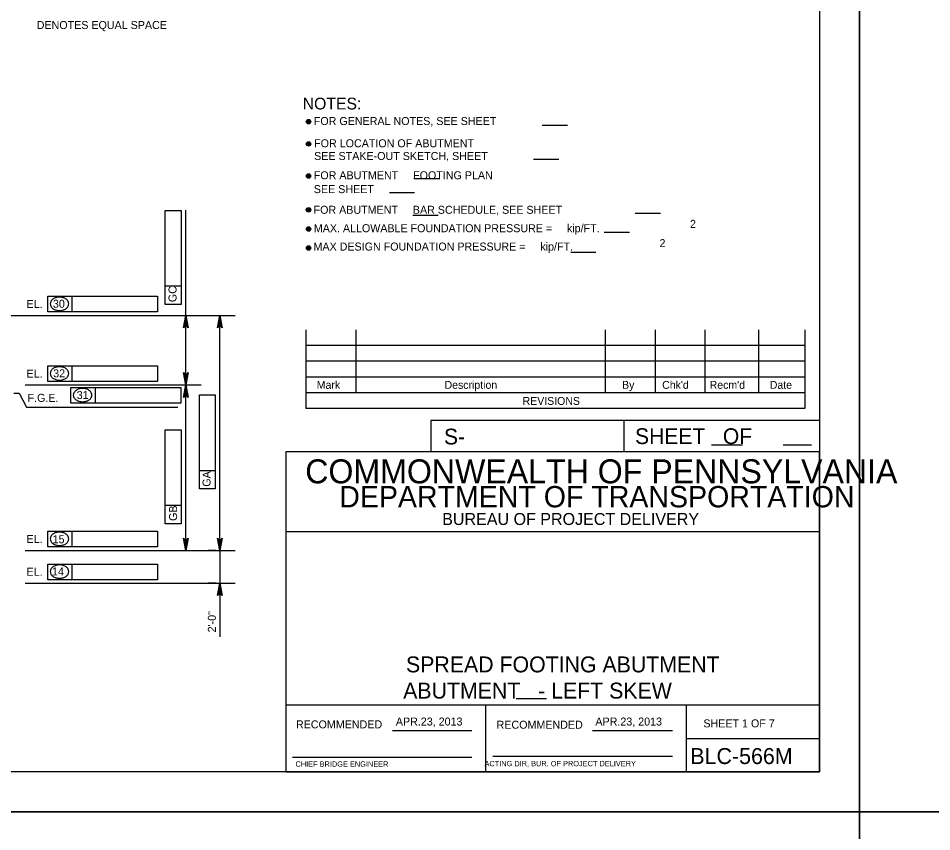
# Model space of a CAD drawing. Extents: x 638255 to 640306, y 296059 to 298435.
# Drawn here: x 638961.1 to 639303.6, y 297834 to 298139 of the extents above; entities that cross this region are included whole.
import ezdxf

# ---------------------------------------------------------------- set-up
doc = ezdxf.new("R2010")
doc.units = 0
for name, color, linetype in [('1', 7, 'Continuous'), ('2', 7, 'Continuous'), ('4', 7, 'Continuous'), ('Level 3', 7, 'Continuous'), ('Level 4', 7, 'Continuous'), ('PLT-BNDY', 7, 'Continuous')]:
    doc.layers.add(name, color=color, linetype=linetype)

# ---------------------------------------------------------------- blocks, each defined once
blk = doc.blocks.new('V')
at = {"layer": '1'}
blk.add_line((0, 0), (0, 0), dxfattribs=at)

msp = doc.modelspace()

# ---------------------------------------------------------------- linework, layer by layer
at = {"layer": '2'}
for p, q in [((639261.46, 298420.46), (639261.46, 297856.46)), ((639068.92, 298022.15), (639068.92, 297992.62)), ((639087.62, 298022.15), (639087.62, 297998.53)), ((639181.13, 298022.15), (639181.13, 297998.53)), ((639199.83, 298022.15), (639199.83, 297998.53)), ((639218.53, 298022.15), (639218.53, 297998.53)), ((639238.59, 298022.15), (639238.59, 297998.53)), ((639255.94, 298022.15), (639255.94, 297992.62)), ((639255.94, 298016.24), (639068.92, 298016.24)), ((639255.94, 298010.34), (639068.92, 298010.34)), ((639255.94, 298004.43), (639068.92, 298004.43)), ((639255.94, 297998.53), (639068.92, 297998.53)), ((639255.94, 297992.62), (639068.92, 297992.62)), ((639261.46, 297988.11), (639115.78, 297988.11)), ((639115.78, 297988.11), (639115.78, 297976.46)), ((639188.09, 297988.11), (639188.09, 297976.46)), ((639220.95, 297979), (639232.6, 297979)), ((639247.83, 297979), (639258.56, 297979)), ((639261.46, 297976.46), (639061.46, 297976.46)), ((639061.46, 297976.46), (639061.46, 297856.46)), ((639261.46, 297856.46), (639261.46, 297976.46)), ((639261.46, 297946.46), (639061.46, 297946.46)), ((639261.46, 297881.46), (639061.46, 297881.46)), ((639136.46, 297856.46), (639136.46, 297881.46)), ((639211.46, 297881.46), (639211.46, 297856.46)), ((639101.42, 297871.96), (639131.19, 297871.96)), ((639176.42, 297871.96), (639206.33, 297871.96)), ((639211.46, 297868.96), (639261.46, 297868.96)), ((639063.96, 297861.96), (639131.19, 297861.96)), ((639139.08, 297862.33), (639206.33, 297862.33)), ((639261.46, 297856.46), (638475.46, 297856.46)), ((639061.46, 297856.46), (639261.46, 297856.46))]:
    msp.add_line(p, q, dxfattribs=at)
at = {"layer": '4'}
msp.add_line((639147.83, 297883.91), (639159.19, 297883.91), dxfattribs=at)
at = {"layer": 'Level 3'}
for p, q in [((639157.57, 298098.88), (639167.02, 298098.88)), ((639154.31, 298086.18), (639163.76, 298086.18)), ((639109.4, 298078.89), (639118.85, 298078.89)), ((639100.26, 298073.62), (639109.71, 298073.62)), ((639016.25, 298066.94), (639022.14, 298066.94)), ((639016.25, 298038.53), (639016.25, 298066.94)), ((639022.14, 298066.94), (639022.14, 298031.7)), ((639023.96, 298001.46), (639023.96, 298066.96)), ((639192.42, 298065.88), (639201.86, 298065.88)), ((639109.04, 298065.1), (639118.49, 298065.1)), ((639180.8, 298058.75), (639190.25, 298058.75)), ((639168.25, 298051.31), (639177.7, 298051.31)), ((639016.25, 298031.7), (639016.25, 298038.53)), ((639022.14, 298038.53), (639016.25, 298038.53)), ((638972.21, 298034.72), (638981.36, 298034.72)), ((638972.21, 298028.83), (638972.21, 298034.72)), ((638981.36, 298028.83), (638981.36, 298034.72)), ((638981.36, 298034.72), (639013.34, 298034.72)), ((639013.34, 298034.72), (639013.34, 298028.83)), ((639022.14, 298031.7), (639016.25, 298031.7)), ((639013.34, 298028.83), (638972.21, 298028.83)), ((638910.57, 298027.55), (639042.49, 298027.55)), ((639021.51, 298027.55), (639028.38, 298027.55)), ((639030.41, 298027.55), (639041.15, 298027.55)), ((639035.64, 298027.55), (639041.15, 298027.55)), ((639036.72, 297939.44), (639036.72, 298027.55)), ((638972.21, 298008.63), (638981.36, 298008.63)), ((638972.21, 298002.73), (638972.21, 298008.63)), ((638981.36, 298002.73), (638981.36, 298008.63)), ((638981.36, 298008.63), (639013.34, 298008.63)), ((639013.34, 298008.63), (639013.34, 298002.73)), ((638963.72, 298001.46), (639029.73, 298001.46)), ((639013.34, 298002.73), (638972.21, 298002.73)), ((639018.63, 298001.46), (639028.38, 298001.46)), ((639023.96, 297939.44), (639023.96, 298001.46)), ((638961.5, 297998.38), (638964.26, 297993.2)), ((638980.88, 298000.5), (638990.04, 298000.5)), ((638980.88, 297994.61), (638980.88, 298000.5)), ((638990.04, 297994.61), (638990.04, 298000.5)), ((638990.04, 298000.5), (639022.01, 298000.5)), ((639022.01, 298000.5), (639022.01, 297994.61)), ((639029.01, 297997.73), (639034.9, 297997.73)), ((639029.01, 297969.33), (639029.01, 297997.73)), ((639034.9, 297997.73), (639034.9, 297962.5)), ((639022.01, 297994.61), (638980.88, 297994.61)), ((638964.26, 297993.2), (639020.96, 297993.2)), ((639016.25, 297984.68), (639022.14, 297984.68)), ((639016.25, 297956.28), (639016.25, 297984.68)), ((639022.14, 297984.68), (639022.14, 297949.45)), ((639029.01, 297962.5), (639029.01, 297969.33)), ((639034.9, 297969.33), (639029.01, 297969.33)), ((639034.9, 297962.5), (639029.01, 297962.5)), ((639016.25, 297949.45), (639016.25, 297956.28)), ((639022.14, 297956.28), (639016.25, 297956.28)), ((639022.14, 297949.45), (639016.25, 297949.45)), ((638972.21, 297946.62), (638981.36, 297946.62)), ((638972.21, 297940.72), (638972.21, 297946.62)), ((638981.36, 297940.72), (638981.36, 297946.62)), ((638981.36, 297946.62), (639013.34, 297946.62)), ((639013.34, 297946.62), (639013.34, 297940.72)), ((638963.72, 297939.44), (639042.49, 297939.44)), ((639013.34, 297940.72), (638972.21, 297940.72)), ((639030.41, 297939.44), (639041.15, 297939.44)), ((639035.25, 297939.44), (639032.3, 297939.44)), ((639035.17, 297939.44), (639041.15, 297939.44)), ((639035.64, 297939.44), (639041.15, 297939.44)), ((639036.72, 297939.44), (639036.72, 297927.16)), ((638972.21, 297928.44), (638972.21, 297934.34)), ((638972.21, 297934.34), (638981.36, 297934.34)), ((638981.36, 297928.44), (638981.36, 297934.34)), ((638981.36, 297934.34), (639013.34, 297934.34)), ((639013.34, 297934.34), (639013.34, 297928.44)), ((638963.72, 297927.16), (639042.49, 297927.16)), ((639013.34, 297928.44), (638972.21, 297928.44)), ((639035.25, 297927.16), (639032.3, 297927.16)), ((639036.72, 297927.16), (639036.72, 297907))]:
    msp.add_line(p, q, dxfattribs=at)
for points in [[(639023.96, 298027.55), (639024.83, 298022.9), (639024.59, 298023.26), (639024.28, 298023.44), (639023.96, 298023.49), (639023.65, 298023.44), (639023.34, 298023.26), (639023.09, 298022.9), (639023.96, 298027.55), (639023.34, 298023.26), (639023.65, 298023.44), (639023.96, 298027.55), (639023.96, 298023.49), (639024.28, 298023.44), (639023.96, 298027.55), (639024.59, 298023.26)], [(639036.72, 298027.55), (639037.6, 298022.9), (639037.35, 298023.26), (639037.04, 298023.44), (639036.72, 298023.49), (639036.41, 298023.44), (639036.1, 298023.26), (639035.85, 298022.9), (639036.72, 298027.55), (639036.1, 298023.26), (639036.41, 298023.44), (639036.72, 298027.55), (639036.72, 298023.49), (639037.04, 298023.44), (639036.72, 298027.55), (639037.35, 298023.26)], [(639023.96, 298001.46), (639023.09, 298006.11), (639023.34, 298005.75), (639023.65, 298005.56), (639023.96, 298005.51), (639024.28, 298005.56), (639024.59, 298005.75), (639024.83, 298006.11), (639023.96, 298001.46), (639024.59, 298005.75), (639024.28, 298005.56), (639023.96, 298001.46), (639023.96, 298005.51), (639023.65, 298005.56), (639023.96, 298001.46), (639023.34, 298005.75)], [(639023.96, 298001.46), (639024.83, 297996.8), (639024.59, 297997.16), (639024.28, 297997.35), (639023.96, 297997.4), (639023.65, 297997.35), (639023.34, 297997.16), (639023.09, 297996.8), (639023.96, 298001.46), (639023.34, 297997.16), (639023.65, 297997.35), (639023.96, 298001.46), (639023.96, 297997.4), (639024.28, 297997.35), (639023.96, 298001.46), (639024.59, 297997.16)], [(639023.96, 297939.44), (639023.09, 297944.09), (639023.34, 297943.74), (639023.65, 297943.55), (639023.96, 297943.5), (639024.28, 297943.55), (639024.59, 297943.74), (639024.83, 297944.09), (639023.96, 297939.44), (639024.59, 297943.74), (639024.28, 297943.55), (639023.96, 297939.44), (639023.96, 297943.5), (639023.65, 297943.55), (639023.96, 297939.44), (639023.34, 297943.74)], [(639036.72, 297939.44), (639035.85, 297944.09), (639036.1, 297943.74), (639036.41, 297943.55), (639036.72, 297943.5), (639037.04, 297943.55), (639037.35, 297943.74), (639037.6, 297944.09), (639036.72, 297939.44), (639037.35, 297943.74), (639037.04, 297943.55), (639036.72, 297939.44), (639036.72, 297943.5), (639036.41, 297943.55), (639036.72, 297939.44), (639036.1, 297943.74)], [(639036.72, 297927.16), (639037.6, 297922.51), (639037.35, 297922.87), (639037.04, 297923.05), (639036.72, 297923.11), (639036.41, 297923.05), (639036.1, 297922.87), (639035.85, 297922.51), (639036.72, 297927.16), (639036.1, 297922.87), (639036.41, 297923.05), (639036.72, 297927.16), (639036.72, 297923.11), (639037.04, 297923.05), (639036.72, 297927.16), (639037.35, 297922.87)]]:
    msp.add_lwpolyline(points, dxfattribs=at)
for points in [[(639023.47, 298024.6), (639024.45, 298024.6), (639023.96, 298027.55)], [(639036.23, 298024.6), (639037.22, 298024.6), (639036.72, 298027.55)], [(639023.47, 298004.4), (639024.45, 298004.4), (639023.96, 298001.46)], [(639023.47, 297998.51), (639024.45, 297998.51), (639023.96, 298001.46)], [(639023.47, 297942.39), (639024.45, 297942.39), (639023.96, 297939.44)], [(639036.23, 297942.39), (639037.22, 297942.39), (639036.72, 297939.44)], [(639036.23, 297924.22), (639037.22, 297924.22), (639036.72, 297927.16)]]:
    msp.add_lwpolyline(points, close=True, dxfattribs=at)
for centre, radius in [((639069.94, 298100.2), 0.832), ((639069.94, 298100.2), 0.624), ((639069.94, 298100.2), 0.416), ((639069.94, 298100.2), 0.208), ((639069.94, 298091.84), 0.832), ((639069.94, 298091.84), 0.624), ((639069.94, 298091.84), 0.416), ((639069.94, 298091.84), 0.208), ((639069.94, 298079.82), 0.832), ((639069.94, 298079.82), 0.624), ((639069.94, 298079.82), 0.416), ((639069.94, 298079.82), 0.208), ((639069.94, 298067.14), 0.832), ((639069.94, 298067.14), 0.624), ((639069.94, 298067.14), 0.416), ((639069.94, 298067.14), 0.208), ((639069.95, 298059.96), 0.832), ((639069.95, 298059.96), 0.624), ((639069.95, 298059.96), 0.416), ((639069.95, 298059.96), 0.208), ((639069.95, 298052.84), 0.832), ((639069.95, 298052.84), 0.624), ((639069.95, 298052.84), 0.416), ((639069.95, 298052.84), 0.208)]:
    msp.add_circle(centre, radius, dxfattribs=at)
for centre, radius, start, end in [((638974.9, 298031.88), 1.82, 149.9767, 180), ((638974.9, 298031.88), 1.82, 180, 210.0233), ((638975.71, 298031.42), 2.75, 125.6316, 149.9767), ((638976.23, 298030.68), 3.65, 106.5358, 125.6316), ((638976.58, 298029.53), 4.86, 90, 106.5358), ((638976.58, 298029.53), 4.86, 73.4642, 90), ((638976.92, 298030.68), 3.65, 54.3684, 73.4642), ((638977.45, 298031.42), 2.75, 30.0233, 54.3684), ((638978.25, 298031.88), 1.82, 0, 30.0233), ((638978.25, 298031.88), 1.82, 329.9767, 0), ((638975.71, 298032.35), 2.75, 210.0233, 234.3684), ((638976.23, 298033.08), 3.65, 234.3684, 253.4642), ((638976.58, 298034.24), 4.86, 253.4642, 270), ((638976.58, 298034.24), 4.86, 270, 286.5358), ((638976.92, 298033.08), 3.65, 286.5358, 305.6316), ((638977.45, 298032.35), 2.75, 305.6316, 329.9767), ((638976.23, 298004.59), 3.65, 106.5358, 125.6316), ((638976.58, 298003.43), 4.86, 90, 106.5358), ((638976.58, 298003.43), 4.86, 73.4642, 90), ((638976.92, 298004.59), 3.65, 54.3684, 73.4642), ((638974.9, 298005.79), 1.82, 149.9767, 180), ((638974.9, 298005.79), 1.82, 180, 210.0233), ((638975.71, 298005.32), 2.75, 125.6316, 149.9767), ((638975.71, 298006.25), 2.75, 210.0233, 234.3684), ((638977.45, 298005.32), 2.75, 30.0233, 54.3684), ((638977.45, 298006.25), 2.75, 305.6316, 329.9767), ((638978.25, 298005.79), 1.82, 0, 30.0233), ((638978.25, 298005.79), 1.82, 329.9767, 0), ((638976.23, 298006.99), 3.65, 234.3684, 253.4642), ((638976.58, 298008.14), 4.86, 253.4642, 270), ((638976.58, 298008.14), 4.86, 270, 286.5358), ((638976.92, 298006.99), 3.65, 286.5358, 305.6316), ((638983.58, 297997.66), 1.82, 149.9767, 180), ((638983.58, 297997.66), 1.82, 180, 210.0233), ((638984.38, 297997.2), 2.75, 125.6316, 149.9767), ((638984.91, 297996.46), 3.65, 106.5358, 125.6316), ((638985.25, 297995.3), 4.86, 90, 106.5358), ((638985.25, 297995.3), 4.86, 73.4642, 90), ((638985.6, 297996.46), 3.65, 54.3684, 73.4642), ((638986.12, 297997.2), 2.75, 30.0233, 54.3684), ((638986.92, 297997.66), 1.82, 0, 30.0233), ((638986.92, 297997.66), 1.82, 329.9767, 0), ((638984.38, 297998.13), 2.75, 210.0233, 234.3684), ((638984.91, 297998.86), 3.65, 234.3684, 253.4642), ((638985.25, 298000.02), 4.86, 253.4642, 270), ((638985.25, 298000.02), 4.86, 270, 286.5358), ((638985.6, 297998.86), 3.65, 286.5358, 305.6316), ((638986.12, 297998.13), 2.75, 305.6316, 329.9767), ((638976.23, 297942.58), 3.65, 106.5358, 125.6316), ((638976.58, 297941.42), 4.86, 90, 106.5358), ((638976.58, 297941.42), 4.86, 73.4642, 90), ((638976.92, 297942.58), 3.65, 54.3684, 73.4642), ((638974.9, 297943.78), 1.82, 149.9767, 180), ((638974.9, 297943.78), 1.82, 180, 210.0233), ((638975.71, 297943.31), 2.75, 125.6316, 149.9767), ((638975.71, 297944.24), 2.75, 210.0233, 234.3684), ((638977.45, 297943.31), 2.75, 30.0233, 54.3684), ((638977.45, 297944.24), 2.75, 305.6316, 329.9767), ((638978.25, 297943.78), 1.82, 0, 30.0233), ((638978.25, 297943.78), 1.82, 329.9767, 0), ((638976.23, 297944.97), 3.65, 234.3684, 253.4642), ((638976.58, 297946.13), 4.86, 253.4642, 270), ((638976.58, 297946.13), 4.86, 270, 286.5358), ((638976.92, 297944.97), 3.65, 286.5358, 305.6316), ((638974.9, 297931.5), 1.82, 149.9767, 180), ((638975.71, 297931.03), 2.75, 125.6316, 149.9767), ((638976.23, 297930.3), 3.65, 106.5358, 125.6316), ((638976.58, 297929.14), 4.86, 90, 106.5358), ((638976.58, 297929.14), 4.86, 73.4642, 90), ((638976.92, 297930.3), 3.65, 54.3684, 73.4642), ((638977.45, 297931.03), 2.75, 30.0233, 54.3684), ((638978.25, 297931.5), 1.82, 0, 30.0233), ((638974.9, 297931.5), 1.82, 180, 210.0233), ((638975.71, 297931.96), 2.75, 210.0233, 234.3684), ((638976.23, 297932.69), 3.65, 234.3684, 253.4642), ((638976.58, 297933.85), 4.86, 253.4642, 270), ((638976.58, 297933.85), 4.86, 270, 286.5358), ((638976.92, 297932.69), 3.65, 286.5358, 305.6316), ((638977.45, 297931.96), 2.75, 305.6316, 329.9767), ((638978.25, 297931.5), 1.82, 329.9767, 0)]:
    msp.add_arc(centre, radius, start, end, dxfattribs=at)
at = {"layer": 'Level 4'}
msp.add_line((638959.44, 297998.38), (638961.5, 297998.38), dxfattribs=at)
at = {"layer": 'PLT-BNDY'}
for points in [[(638435.46, 298435.46), (639276.46, 298435.46), (639276.46, 297841.46), (638435.46, 297841.46)], [(639276.46, 298435.46), (640117.46, 298435.46), (640117.46, 297841.46), (639276.46, 297841.46)], [(638435.46, 297841.46), (639276.46, 297841.46), (639276.46, 297247.46), (638435.46, 297247.46)], [(639276.46, 297841.46), (640117.46, 297841.46), (640117.46, 297247.46), (639276.46, 297247.46)]]:
    msp.add_lwpolyline(points, close=True, dxfattribs=at)

# ---------------------------------------------------------------- block references
at = {"layer": 'Level 3', "xscale": 0.7859001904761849, "yscale": 0.785900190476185}
msp.add_blockref('V', (638997.84, 297934.19), dxfattribs=at)

# ---------------------------------------------------------------- texts
at = {"layer": '2'}
for s, height, p in [('Mark', 2.952, (639073.02, 298000.03)), ('Description', 2.9523, (639120.92, 298000.03)), ('By', 2.952, (639187.49, 298000.03)), ("Chk'd", 2.952, (639202.52, 298000.03)), ("Recm'd", 2.953, (639220.33, 298000.03)), ('Date', 2.952, (639242.86, 298000.03)), ('REVISIONS', 2.952, (639150.2, 297994.01)), ('S-', 5.905, (639120.73, 297979.17)), ('SHEET   OF', 5.907, (639192.35, 297979.31)), ('COMMONWEALTH OF PENNSYLVANIA', 9, (639068.71, 297964.58)), ('DEPARTMENT OF TRANSPORTATION', 8.0002, (639081.46, 297955.58)), ('BUREAU OF PROJECT DELIVERY', 4.5, (639120.05, 297948.96)), ('ABUTMENT   - LEFT SKEW', 5.9728, (639105.42, 297883.88)), ('APR.23, 2013', 3, (639102.67, 297873.77)), ('APR.23, 2013', 3, (639177.48, 297873.77)), ('SHEET 1 OF 7', 3, (639217.97, 297873.08)), ('BLC-566M', 6, (639213.08, 297859.33)), ('CHIEF BRIDGE ENGINEER', 2.0002, (639065.05, 297858.33)), ('  ACTING DIR, BUR. OF PROJECT DELIVERY', 2.0002, (639134.36, 297858.51))]:
    msp.add_text(s, height=height, dxfattribs=at).set_placement(p)
for p in [(639065.23, 297872.71), (639140.44, 297872.58)]:
    msp.add_text('RECOMMENDED', height=3, rotation=360, dxfattribs=at).set_placement(p)
at = {"layer": '4'}
msp.add_text('SPREAD FOOTING ABUTMENT', height=5.9728, dxfattribs=at).set_placement((639106.47, 297893.71))
at = {"layer": 'Level 3'}
for s, height, p in [('DENOTES EQUAL SPACE', 3.0001, (638968.03, 298134.93)), ('NOTES:', 4.421, (639067.75, 298104.76)), ('FOR GENERAL NOTES, SEE SHEET    ', 3.0001, (639071.92, 298098.93)), ('FOR LOCATION OF ABUTMENT', 3.0001, (639072.04, 298090.59)), ('SEE STAKE-OUT SKETCH, SHEET    ', 3.0001, (639072.04, 298085.82)), ('FOR ABUTMENT     FOOTING PLAN', 3.0001, (639071.92, 298078.59)), ('SEE SHEET    ', 3.0001, (639071.92, 298073.4)), ('FOR ABUTMENT     BAR SCHEDULE, SEE SHEET    ', 3.0001, (639071.83, 298065.65)), ('2', 2.99, (639212.95, 298060.38)), ('MAX. ALLOWABLE FOUNDATION PRESSURE =     kip/FT. ', 2.9943, (639071.93, 298058.74)), ('2', 2.99, (639201.53, 298053.17)), ('MAX DESIGN FOUNDATION PRESSURE =     kip/FT. ', 3.0001, (639071.8, 298051.86)), ('EL.', 3, (638964.2, 298030.31)), ('30', 3, (638974.11, 298030.42)), ('EL.', 3, (638964.2, 298004.21)), ('32', 3, (638974.22, 298004.33)), ('F.G.E.', 3, (638964.59, 297995.14)), ('31', 3, (638983.03, 297996.2)), ('EL.', 3, (638964.2, 297942.2)), ('15', 3, (638973.99, 297942.12)), ('EL.', 3, (638964.2, 297929.92)), ('14', 3, (638973.77, 297930.04))]:
    msp.add_text(s, height=height, dxfattribs=at).set_placement(p)
for s, p in [('GC', (639020.45, 298032.53)), ('GA', (639033.21, 297963.32)), ('GB', (639020.66, 297950.49)), ('2\'-0"', (639035.19, 297908.7))]:
    msp.add_text(s, height=3, rotation=90, dxfattribs=at).set_placement(p)

doc.saveas('drawing.dxf')
